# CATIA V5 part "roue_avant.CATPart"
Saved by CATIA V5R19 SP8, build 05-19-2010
Part number: roue_avant
Bounding box of the stored display mesh (mm): x -59.975 to 59.975, y -59.975 to 59.975, z -25 to 25
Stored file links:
  U:\Thinkmotion\Assemblage final\roue_avant.CATPart
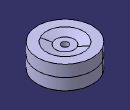
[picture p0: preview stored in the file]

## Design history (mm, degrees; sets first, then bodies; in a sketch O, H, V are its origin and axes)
Body1 (main body)
  Sketch1 on yz-plane, origin (0, 0, 0), H (0, 1, 0), V (0, 0, 1)
    line L1 (0, 0) -> (0, 20)
    point P1 (0, 20)
    line L2 (0, 20) -> (-20, 20)
    point P2 (-20, 20)
    line L3 (-20, 20) -> (-40, 25)
    point P3 (-40, 25)
    line L4 (-40, 25) -> (-60, 25)
    point P4 (-60, 25)
    line L5 (-60, 25) -> (-60, 0)
    point P5 (-60, 0)
    reference intersected line E1 through (0, 0) direction (-1, 0) from xy-plane
    point P8 (0, -20)
    point P9 (-20, -20)
    point P10 (-40, -25)
    point P11 (-60, -25)
    point P12 (-60, 0)
    point P13 (0, 0)
    line L6 (0, 0) -> (0, -20)
    line L7 (0, -20) -> (-20, -20)
    line L8 (-20, -20) -> (-40, -25)
    line L9 (-40, -25) -> (-60, -25)
    line L10 (-60, -25) -> (-60, 0)
    length L2 = 20
    length L4 = 20
    distance L1 L5 = 60
    length L5 = 25
    vertical: L1 V, L5 V
    horizontal: L2 H, L4 H
    symmetry: P1 P8 E1, P2 P9 E1, P3 P10 E1, P4 P11 E1, P5 P12 E1, O P13 E1, L1 L6 E1, L2 L7 E1, L3 L8 E1, L4 L9 E1, L5 L10 E1
    coincidence: O P13, P5 P12
  Shaft1: profile Sketch1, axis Sketch1.L6, angle 360
  Sketch2 on face of Shaft1 from Sketch1.L2, origin (0, 0, 20), H (1, 0, 0), V (0, 1, 0)
    point P1 (0, 0)
    coincidence: P1 V, P1 H
  Hole1: placed by Sketch2, at (0, 0, 20) direction (0, 0, -1), diameter 15, through (limit type 3)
